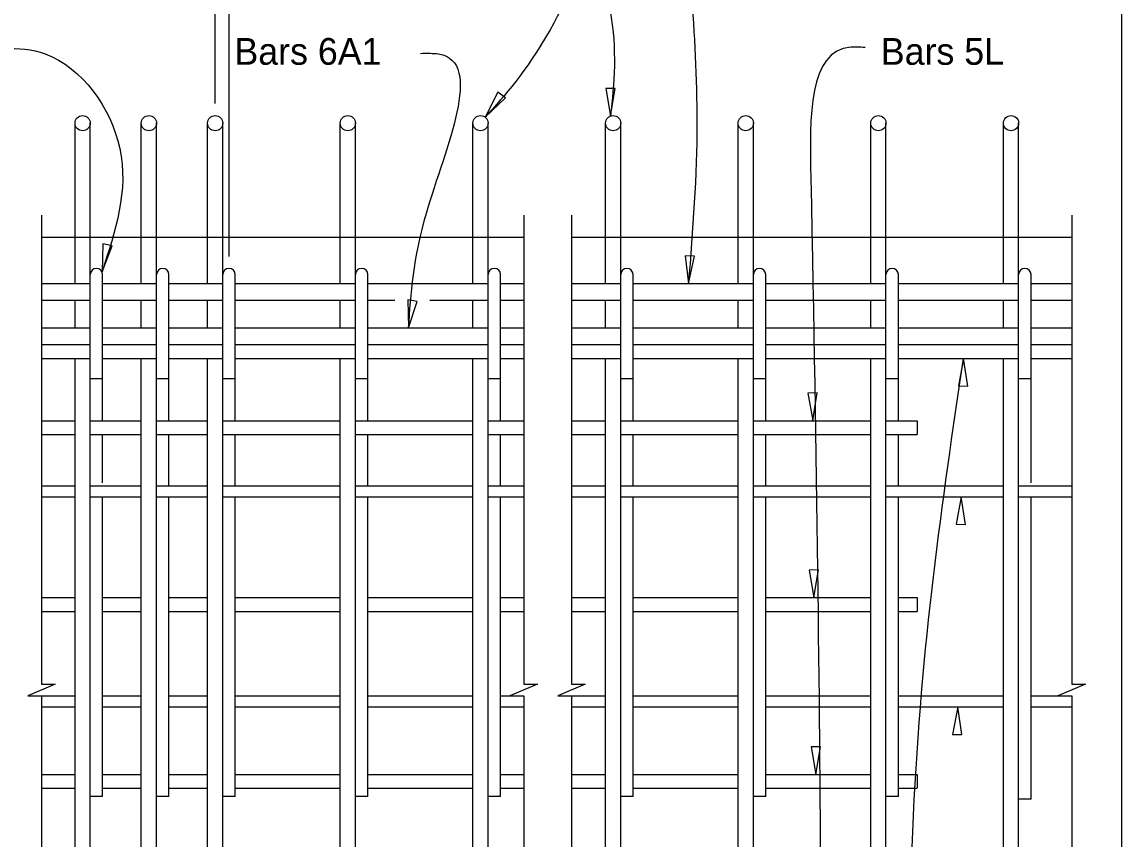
# Model space of a CAD drawing. Extents: x 120735 to 120771, y 120670.1 to 120685.4.
# Drawn here: x 120751.37 to 120755.517, y 120679.152 to 120682.233 of the extents above; entities that cross this region are included whole.
import ezdxf

# ---------------------------------------------------------------- set-up
doc = ezdxf.new("R2010")
doc.units = 0
for name, color, linetype in [('ActivePts-ConstElements', 7, 'Continuous'), ('BeamConc', 7, 'Continuous'), ('Dimension', 7, 'Continuous'), ('Rebar', 7, 'Continuous'), ('TextStructures', 7, 'Continuous')]:
    doc.layers.add(name, color=color, linetype=linetype)

msp = doc.modelspace()

# ---------------------------------------------------------------- linework, layer by layer
at = {"layer": 'ActivePts-ConstElements'}
msp.add_lwpolyline([(120734.9918, 120671.4068), (120755.5171, 120671.4068), (120755.5171, 120684.3798), (120734.9918, 120684.3798)], close=True, dxfattribs=at)
at = {"layer": 'BeamConc'}
for p, q in [((120751.4437, 120681.4214), (120753.2615, 120681.4214)), ((120753.4416, 120681.4214), (120755.3273, 120681.4214))]:
    msp.add_line(p, q, dxfattribs=at)
at = {"layer": 'Dimension'}
for p, q in [((120752.1508, 120681.3478), (120752.1508, 120683.0239)), ((120752.0987, 120681.9253), (120752.0987, 120682.8643))]:
    msp.add_line(p, q, dxfattribs=at)
for points in [[(120753.1164, 120681.8741), (120753.1926, 120681.9472), (120753.1643, 120681.9683)], [(120753.5894, 120681.8779), (120753.6064, 120681.9821), (120753.5711, 120681.9819)], [(120751.672, 120681.2899), (120751.7097, 120681.3886), (120751.6751, 120681.3955)], [(120753.8826, 120681.246), (120753.9057, 120681.349), (120753.8705, 120681.3509)], [(120752.8268, 120681.0788), (120752.8603, 120681.1789), (120752.8254, 120681.1844)], [(120754.9194, 120680.9642), (120754.9003, 120680.8603), (120754.9355, 120680.8598)], [(120754.3511, 120680.7294), (120754.3681, 120680.8337), (120754.3328, 120680.8334)], [(120754.9113, 120680.4422), (120754.8921, 120680.3384), (120754.9274, 120680.3379)], [(120754.3555, 120680.062), (120754.3725, 120680.1662), (120754.3372, 120680.166)], [(120754.8977, 120679.6501), (120754.8786, 120679.5462), (120754.9139, 120679.5457)], [(120754.3633, 120679.3952), (120754.3803, 120679.4994), (120754.345, 120679.4992)]]:
    msp.add_lwpolyline(points, close=True, dxfattribs=at)
for points in [[(120751.4437, 120681.5047), (120751.4437, 120679.7363), (120751.4954, 120679.7363), (120751.392, 120679.6913), (120751.4437, 120679.6913), (120751.4437, 120678.0689), (120751.4954, 120678.0689), (120751.392, 120678.0239), (120751.4437, 120678.0239), (120751.4437, 120676.083)], [(120753.2616, 120681.5047), (120753.2616, 120679.7363), (120753.3132, 120679.7363), (120753.2099, 120679.6913), (120753.2616, 120679.6913), (120753.2616, 120678.0689), (120753.3132, 120678.0689), (120753.2099, 120678.0239), (120753.2616, 120678.0239), (120753.2616, 120676.1041)], [(120753.4416, 120681.5047), (120753.4416, 120679.7363), (120753.4933, 120679.7363), (120753.3899, 120679.6913), (120753.4416, 120679.6913), (120753.4416, 120678.0689), (120753.4933, 120678.0689), (120753.3899, 120678.0239), (120753.4416, 120678.0239), (120753.4416, 120676.1041)], [(120755.3274, 120681.5047), (120755.3274, 120679.7363), (120755.3791, 120679.7363), (120755.2757, 120679.6913), (120755.3274, 120679.6913), (120755.3274, 120677.9439), (120755.3791, 120677.9439), (120755.2757, 120677.8989), (120755.3274, 120677.8989), (120755.3274, 120676.083)]]:
    msp.add_lwpolyline(points, dxfattribs=at)
for points in [[(120753.3948, 120682.5203), (120753.4201, 120682.5203), (120753.3608, 120682.2036), (120753.1164, 120681.8741)], [(120753.3948, 120682.5204), (120753.436, 120682.5205), (120753.587, 120682.2774), (120753.5894, 120681.8779)], [(120753.8935, 120682.3527), (120753.9147, 120681.8549), (120753.8826, 120681.246)], [(120751.1329, 120682.1134), (120751.458, 120682.1121), (120751.7391, 120681.7555), (120751.672, 120681.2899)], [(120754.549, 120682.1363), (120754.4946, 120682.1374), (120754.3442, 120681.6429), (120754.3814, 120676.8901)], [(120752.8729, 120682.1143), (120752.9409, 120682.1121), (120752.8948, 120681.5143), (120752.8267, 120681.0788)], [(120754.6436, 120675.9942), (120754.6867, 120675.9942), (120754.8511, 120676.9318), (120754.9193, 120680.9642)]]:
    msp.add_spline(points, degree=3, dxfattribs=at)
at = {"layer": 'Rebar'}
for p, q in [((120751.5701, 120681.246), (120751.5701, 120681.851)), ((120751.6274, 120676.3667), (120751.6274, 120681.851)), ((120751.8201, 120681.246), (120751.8201, 120681.851)), ((120751.8774, 120676.3667), (120751.8774, 120681.851)), ((120752.0701, 120681.246), (120752.0701, 120681.851)), ((120752.1274, 120676.3667), (120752.1274, 120681.851)), ((120752.5701, 120681.246), (120752.5701, 120681.851)), ((120752.6274, 120676.3667), (120752.6274, 120681.851)), ((120753.0701, 120681.246), (120753.0701, 120681.851)), ((120753.1274, 120676.3667), (120753.1274, 120681.851)), ((120753.5701, 120681.246), (120753.5701, 120681.851)), ((120753.6274, 120676.3667), (120753.6274, 120681.851)), ((120754.0701, 120681.246), (120754.0701, 120681.851)), ((120754.1274, 120676.3667), (120754.1274, 120681.851)), ((120754.5701, 120681.246), (120754.5701, 120681.851)), ((120754.6274, 120676.3667), (120754.6274, 120681.851)), ((120755.0701, 120681.246), (120755.0701, 120681.851)), ((120755.1274, 120676.3667), (120755.1274, 120681.851)), ((120751.6742, 120680.7287), (120751.6742, 120681.2799)), ((120751.9242, 120680.7287), (120751.9242, 120681.2799)), ((120752.1742, 120680.7287), (120752.1742, 120681.2799)), ((120752.6742, 120680.7287), (120752.6742, 120681.2799)), ((120753.1742, 120680.7287), (120753.1742, 120681.2799)), ((120753.6742, 120680.7287), (120753.6742, 120681.2799)), ((120754.1742, 120680.7287), (120754.1742, 120681.2799)), ((120754.6742, 120680.7287), (120754.6742, 120681.2799)), ((120755.1742, 120680.4943), (120755.1742, 120681.2799)), ((120751.4437, 120681.246), (120751.6274, 120681.246)), ((120751.6742, 120681.246), (120751.8774, 120681.246)), ((120751.9242, 120681.246), (120752.1274, 120681.246)), ((120752.1742, 120681.246), (120752.6274, 120681.246)), ((120752.6742, 120681.246), (120753.1274, 120681.246)), ((120753.1742, 120681.246), (120753.2615, 120681.246)), ((120753.4416, 120681.246), (120753.6274, 120681.246)), ((120753.6742, 120681.246), (120754.1274, 120681.246)), ((120754.1742, 120681.246), (120754.6274, 120681.246)), ((120754.6742, 120681.246), (120755.1274, 120681.246)), ((120755.1742, 120681.246), (120755.3273, 120681.246)), ((120751.4437, 120681.1835), (120751.6274, 120681.1835)), ((120751.5701, 120681.0788), (120751.5701, 120681.1835)), ((120751.6742, 120681.1835), (120751.8774, 120681.1835)), ((120751.8201, 120681.0788), (120751.8201, 120681.1835)), ((120751.9242, 120681.1835), (120752.1274, 120681.1835)), ((120752.0701, 120681.0788), (120752.0701, 120681.1835)), ((120752.1742, 120681.1835), (120752.6274, 120681.1835)), ((120752.5701, 120681.0788), (120752.5701, 120681.1835)), ((120752.6742, 120681.1835), (120752.7762, 120681.1835)), ((120752.9079, 120681.1835), (120753.1274, 120681.1835)), ((120753.0701, 120681.0788), (120753.0701, 120681.1835)), ((120753.1742, 120681.1835), (120753.2615, 120681.1835)), ((120753.4416, 120681.1835), (120753.6274, 120681.1835)), ((120753.5701, 120681.0788), (120753.5701, 120681.1835)), ((120753.6742, 120681.1835), (120754.1274, 120681.1835)), ((120754.0701, 120681.0788), (120754.0701, 120681.1835)), ((120754.1742, 120681.1835), (120754.6274, 120681.1835)), ((120754.5701, 120681.0788), (120754.5701, 120681.1835)), ((120754.6742, 120681.1835), (120755.1274, 120681.1835)), ((120755.0701, 120681.0788), (120755.0701, 120681.1835)), ((120755.1742, 120681.1835), (120755.3273, 120681.1835)), ((120751.4437, 120681.0788), (120751.6274, 120681.0788)), ((120751.6742, 120681.0788), (120751.8774, 120681.0788)), ((120751.9242, 120681.0788), (120752.1274, 120681.0788)), ((120752.1742, 120681.0788), (120752.6274, 120681.0788)), ((120752.6742, 120681.0788), (120753.1274, 120681.0788)), ((120753.1742, 120681.0788), (120753.2615, 120681.0788)), ((120753.4416, 120681.0788), (120753.6274, 120681.0788)), ((120753.6742, 120681.0788), (120754.1274, 120681.0788)), ((120754.1742, 120681.0788), (120754.6274, 120681.0788)), ((120754.6742, 120681.0788), (120755.1274, 120681.0788)), ((120755.1742, 120681.0788), (120755.3273, 120681.0788)), ((120751.4437, 120681.0163), (120751.6274, 120681.0163)), ((120751.6742, 120681.0163), (120751.8774, 120681.0163)), ((120751.9242, 120681.0163), (120752.1274, 120681.0163)), ((120752.1742, 120681.0163), (120752.6274, 120681.0163)), ((120752.6742, 120681.0163), (120753.1274, 120681.0163)), ((120753.1742, 120681.0163), (120753.2615, 120681.0163)), ((120753.4416, 120681.0163), (120753.6274, 120681.0163)), ((120753.6742, 120681.0163), (120754.1274, 120681.0163)), ((120754.1742, 120681.0163), (120754.6274, 120681.0163)), ((120754.6742, 120681.0163), (120755.1274, 120681.0163)), ((120755.1742, 120681.0163), (120755.3273, 120681.0163)), ((120751.4437, 120680.9642), (120751.6274, 120680.9642)), ((120751.5701, 120676.3667), (120751.5701, 120680.9642)), ((120751.6742, 120680.9642), (120751.8774, 120680.9642)), ((120751.8201, 120676.3667), (120751.8201, 120680.9642)), ((120751.9242, 120680.9642), (120752.1274, 120680.9642)), ((120752.0701, 120676.3667), (120752.0701, 120680.9642)), ((120752.1742, 120680.9642), (120752.6274, 120680.9642)), ((120752.5701, 120676.3667), (120752.5701, 120680.9642)), ((120752.6742, 120680.9642), (120753.1274, 120680.9642)), ((120753.0701, 120676.3667), (120753.0701, 120680.9642)), ((120753.1742, 120680.9642), (120753.2615, 120680.9642)), ((120753.4416, 120680.9642), (120753.6274, 120680.9642)), ((120753.5701, 120676.3667), (120753.5701, 120680.9642)), ((120753.6742, 120680.9642), (120754.1274, 120680.9642)), ((120754.0701, 120676.3667), (120754.0701, 120680.9642)), ((120754.1742, 120680.9642), (120754.6274, 120680.9642)), ((120754.5701, 120676.3667), (120754.5701, 120680.9642)), ((120754.6742, 120680.9642), (120755.1274, 120680.9642)), ((120755.0701, 120676.3667), (120755.0701, 120680.9642)), ((120755.1742, 120680.9642), (120755.3273, 120680.9642)), ((120751.6742, 120680.887), (120751.6274, 120680.887)), ((120751.9242, 120680.887), (120751.8774, 120680.887)), ((120752.1742, 120680.887), (120752.1274, 120680.887)), ((120752.6742, 120680.887), (120752.6274, 120680.887)), ((120753.1742, 120680.887), (120753.1274, 120680.887)), ((120753.6742, 120680.887), (120753.6274, 120680.887)), ((120754.1742, 120680.887), (120754.1274, 120680.887)), ((120754.6742, 120680.887), (120754.6274, 120680.887)), ((120755.1742, 120680.887), (120755.1274, 120680.887)), ((120751.4437, 120680.7287), (120751.5701, 120680.7287)), ((120751.6274, 120680.7287), (120751.8201, 120680.7287)), ((120751.8774, 120680.7287), (120752.0701, 120680.7287)), ((120752.1274, 120680.7287), (120752.5701, 120680.7287)), ((120752.6274, 120680.7287), (120753.0701, 120680.7287)), ((120753.1274, 120680.7287), (120753.2615, 120680.7287)), ((120753.4416, 120680.7287), (120753.5701, 120680.7287)), ((120753.6274, 120680.7287), (120754.0701, 120680.7287)), ((120754.1274, 120680.7287), (120754.5701, 120680.7287)), ((120754.6274, 120680.7287), (120754.7446, 120680.7287)), ((120754.7446, 120680.7287), (120754.7446, 120680.6766)), ((120751.4437, 120680.6766), (120751.5701, 120680.6766)), ((120751.6274, 120680.6766), (120751.8201, 120680.6766)), ((120751.6742, 120680.4943), (120751.6742, 120680.6766)), ((120751.8774, 120680.6766), (120752.0701, 120680.6766)), ((120751.9242, 120680.4839), (120751.9242, 120680.6766)), ((120752.1274, 120680.6766), (120752.5701, 120680.6766)), ((120752.1742, 120680.4839), (120752.1742, 120680.6766)), ((120752.6274, 120680.6766), (120753.0701, 120680.6766)), ((120752.6742, 120680.4839), (120752.6742, 120680.6766)), ((120753.1274, 120680.6766), (120753.2615, 120680.6766)), ((120753.1742, 120680.4839), (120753.1742, 120680.6766)), ((120753.4416, 120680.6766), (120753.5701, 120680.6766)), ((120753.6274, 120680.6766), (120754.0701, 120680.6766)), ((120753.6742, 120680.4839), (120753.6742, 120680.6766)), ((120754.1274, 120680.6766), (120754.5701, 120680.6766)), ((120754.1742, 120680.4839), (120754.1742, 120680.6766)), ((120754.6274, 120680.6766), (120754.7446, 120680.6766)), ((120754.6742, 120680.4839), (120754.6742, 120680.6766)), ((120751.4437, 120680.4839), (120751.5701, 120680.4839)), ((120751.6274, 120680.4839), (120751.8201, 120680.4839)), ((120751.8774, 120680.4839), (120752.0701, 120680.4839)), ((120752.1274, 120680.4839), (120752.5701, 120680.4839)), ((120752.6274, 120680.4839), (120753.0701, 120680.4839)), ((120753.1274, 120680.4839), (120753.2615, 120680.4839)), ((120753.4416, 120680.4839), (120753.5701, 120680.4839)), ((120753.6274, 120680.4839), (120754.0701, 120680.4839)), ((120754.1274, 120680.4839), (120754.5701, 120680.4839)), ((120754.6274, 120680.4839), (120755.0701, 120680.4839)), ((120755.1274, 120680.4839), (120755.3273, 120680.4839)), ((120751.4437, 120680.4422), (120751.5701, 120680.4422)), ((120751.6274, 120680.4422), (120751.8201, 120680.4422)), ((120751.6742, 120679.3119), (120751.6742, 120680.4422)), ((120751.8774, 120680.4422), (120752.0701, 120680.4422)), ((120751.9242, 120679.3119), (120751.9242, 120680.4422)), ((120752.1274, 120680.4422), (120752.5701, 120680.4422)), ((120752.1742, 120679.3119), (120752.1742, 120680.4422)), ((120752.6274, 120680.4422), (120753.0701, 120680.4422)), ((120752.6742, 120679.3119), (120752.6742, 120680.4422)), ((120753.1274, 120680.4422), (120753.2615, 120680.4422)), ((120753.1742, 120679.3119), (120753.1742, 120680.4422)), ((120753.4416, 120680.4422), (120753.5701, 120680.4422)), ((120753.6274, 120680.4422), (120754.0701, 120680.4422)), ((120753.6742, 120679.3119), (120753.6742, 120680.4422)), ((120754.1274, 120680.4422), (120754.5701, 120680.4422)), ((120754.1742, 120679.3119), (120754.1742, 120680.4422)), ((120754.6274, 120680.4422), (120755.0701, 120680.4422)), ((120754.6742, 120679.3119), (120754.6742, 120680.4422)), ((120755.1274, 120680.4422), (120755.3273, 120680.4422)), ((120755.1742, 120679.3016), (120755.1742, 120680.4422)), ((120751.4437, 120680.062), (120751.5701, 120680.062)), ((120751.6742, 120680.062), (120751.8201, 120680.062)), ((120751.9242, 120680.062), (120752.0701, 120680.062)), ((120752.1742, 120680.062), (120752.5701, 120680.062)), ((120752.6742, 120680.062), (120753.0701, 120680.062)), ((120753.1742, 120680.062), (120753.2615, 120680.062)), ((120753.4416, 120680.062), (120753.5701, 120680.062)), ((120753.6742, 120680.062), (120754.0701, 120680.062)), ((120754.1742, 120680.062), (120754.5701, 120680.062)), ((120754.6742, 120680.062), (120754.7446, 120680.062)), ((120754.7446, 120680.062), (120754.7446, 120680.0099)), ((120751.4437, 120680.0099), (120751.5701, 120680.0099)), ((120751.6742, 120680.0099), (120751.8201, 120680.0099)), ((120751.9242, 120680.0099), (120752.0701, 120680.0099)), ((120752.1742, 120680.0099), (120752.5701, 120680.0099)), ((120752.6742, 120680.0099), (120753.0701, 120680.0099)), ((120753.1742, 120680.0099), (120753.2615, 120680.0099)), ((120753.4416, 120680.0099), (120753.5701, 120680.0099)), ((120753.6742, 120680.0099), (120754.0701, 120680.0099)), ((120754.1742, 120680.0099), (120754.5701, 120680.0099)), ((120754.6742, 120680.0099), (120754.7446, 120680.0099)), ((120751.4437, 120679.6922), (120751.5701, 120679.6922)), ((120751.6742, 120679.6922), (120751.8201, 120679.6922)), ((120751.9242, 120679.6922), (120752.0701, 120679.6922)), ((120752.1742, 120679.6922), (120752.5701, 120679.6922)), ((120752.6742, 120679.6922), (120753.0701, 120679.6922)), ((120753.1742, 120679.6922), (120753.2615, 120679.6922)), ((120753.4416, 120679.6922), (120753.5701, 120679.6922)), ((120753.6742, 120679.6922), (120754.0701, 120679.6922)), ((120754.1742, 120679.6922), (120754.5701, 120679.6922)), ((120754.6742, 120679.6922), (120755.0701, 120679.6922)), ((120755.1742, 120679.6922), (120755.3273, 120679.6922)), ((120751.4437, 120679.6505), (120751.5701, 120679.6505)), ((120751.6742, 120679.6505), (120751.8201, 120679.6505)), ((120751.9242, 120679.6505), (120752.0701, 120679.6505)), ((120752.1742, 120679.6505), (120752.5701, 120679.6505)), ((120752.6742, 120679.6505), (120753.0701, 120679.6505)), ((120753.1742, 120679.6505), (120753.2615, 120679.6505)), ((120753.4416, 120679.6505), (120753.5701, 120679.6505)), ((120753.6742, 120679.6505), (120754.0701, 120679.6505)), ((120754.1742, 120679.6505), (120754.5701, 120679.6505)), ((120754.6742, 120679.6505), (120755.0701, 120679.6505)), ((120755.1742, 120679.6505), (120755.3273, 120679.6505)), ((120751.4437, 120679.3953), (120751.5701, 120679.3953)), ((120751.6742, 120679.3953), (120751.8201, 120679.3953)), ((120751.9242, 120679.3953), (120752.0701, 120679.3953)), ((120752.1742, 120679.3953), (120752.5701, 120679.3953)), ((120752.6742, 120679.3953), (120753.0701, 120679.3953)), ((120753.1742, 120679.3953), (120753.2615, 120679.3953)), ((120753.4416, 120679.3953), (120753.5701, 120679.3953)), ((120753.6742, 120679.3953), (120754.0701, 120679.3953)), ((120754.1742, 120679.3953), (120754.5701, 120679.3953)), ((120754.6742, 120679.3953), (120754.7446, 120679.3953)), ((120754.7446, 120679.3953), (120754.7446, 120679.3432)), ((120751.4437, 120679.3432), (120751.5701, 120679.3432)), ((120751.6742, 120679.3119), (120751.6274, 120679.3119)), ((120751.6742, 120679.3432), (120751.8201, 120679.3432)), ((120751.9242, 120679.3119), (120751.8774, 120679.3119)), ((120751.9242, 120679.3432), (120752.0701, 120679.3432)), ((120752.1742, 120679.3119), (120752.1274, 120679.3119)), ((120752.1742, 120679.3432), (120752.5701, 120679.3432)), ((120752.6742, 120679.3119), (120752.6274, 120679.3119)), ((120752.6742, 120679.3432), (120753.0701, 120679.3432)), ((120753.1742, 120679.3119), (120753.1274, 120679.3119)), ((120753.1742, 120679.3432), (120753.2615, 120679.3432)), ((120753.4416, 120679.3432), (120753.5701, 120679.3432)), ((120753.6742, 120679.3119), (120753.6274, 120679.3119)), ((120753.6742, 120679.3432), (120754.0701, 120679.3432)), ((120754.1742, 120679.3119), (120754.1274, 120679.3119)), ((120754.1742, 120679.3432), (120754.5701, 120679.3432)), ((120754.6742, 120679.3119), (120754.6274, 120679.3119)), ((120754.6742, 120679.3432), (120754.7446, 120679.3432)), ((120755.1742, 120679.3016), (120755.1274, 120679.3016))]:
    msp.add_line(p, q, dxfattribs=at)
for centre in [(120751.5987, 120681.851), (120751.8487, 120681.851), (120752.0987, 120681.851), (120752.5987, 120681.851), (120753.0987, 120681.851), (120753.5987, 120681.851), (120754.0987, 120681.851), (120754.5987, 120681.851), (120755.0987, 120681.851)]:
    msp.add_circle(centre, 0.0286, dxfattribs=at)
for centre in [(120751.6508, 120681.2799), (120751.9008, 120681.2799), (120752.1508, 120681.2799), (120752.6508, 120681.2799), (120753.1508, 120681.2799), (120753.6508, 120681.2799), (120754.1508, 120681.2799), (120754.6508, 120681.2799), (120755.1508, 120681.2799)]:
    msp.add_arc(centre, 0.0234, 0, 180, dxfattribs=at)

# ---------------------------------------------------------------- texts
at = {"layer": 'TextStructures'}
for s, p in [('Bars 6A1', (120752.1711, 120682.0714)), ('Bars 5L', (120754.6079, 120682.0712))]:
    msp.add_text(s, height=0.1008, dxfattribs=at).set_placement(p)

doc.saveas('drawing.dxf')
